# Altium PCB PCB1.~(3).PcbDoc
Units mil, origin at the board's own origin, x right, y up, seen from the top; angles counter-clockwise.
Board outline 6000 x 4000 mil, 2 copper layers (Top Layer, Bottom Layer); 43 components, 31 nets, 112 pads, 0 vias.
Unrouted connection lines stored in the file: 99.
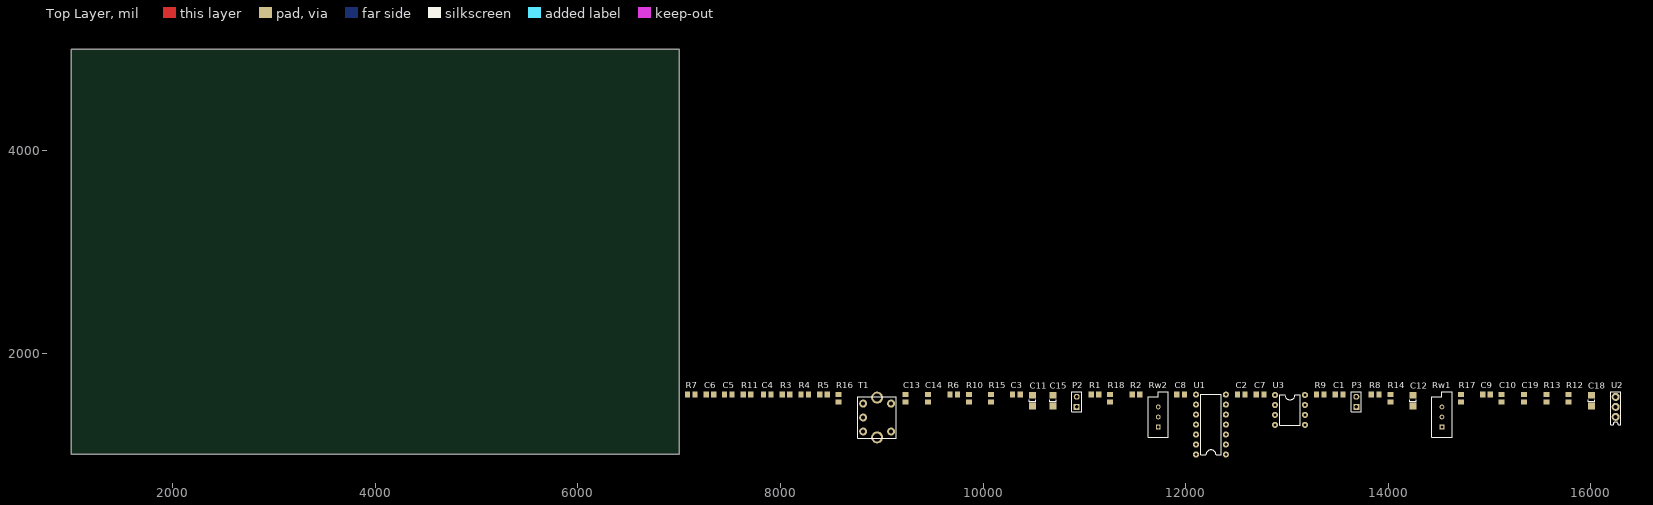
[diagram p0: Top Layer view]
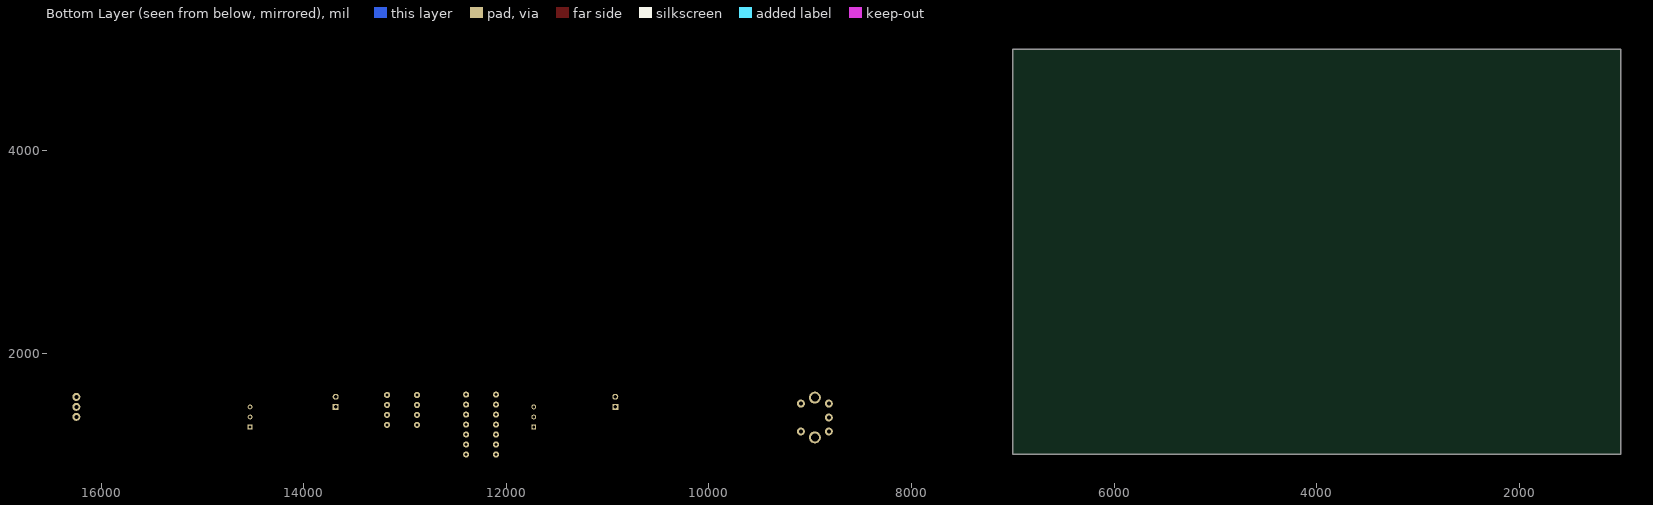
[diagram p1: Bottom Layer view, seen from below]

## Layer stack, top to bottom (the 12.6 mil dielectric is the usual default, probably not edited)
Top Layer: signal copper 1.4
Dielectric: dielectric 12.6, FR-4, Dk 4.8
Bottom Layer: signal copper 1.4

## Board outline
1000,1000 7000,1000 7000,5000 1000,5000

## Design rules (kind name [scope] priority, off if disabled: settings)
Clearance [All] p1: gap=10
PolygonConnect [All] p1: connectstyle=Relief reliefconductorwidth=10 reliefentries=4 polygonreliefangle="90 Angle"
RoomDefinition Sheet1 [InComponentClass('Sheet1')] p1: confinementstyle=ConfineIn formatcopy=TRUE lockcomponents=FALSE outline 7045,960 16315,960 16315,2560 7045,2560
RoutingVias [All] p1: holewidth=28 width=50 viastyle="Through Hole" minholewidth=28 minwidth=50 maxholewidth=28 maxwidth=50
SilkscreenOverComponentPads [All] p1: minsilkscreentomaskgap=10
SolderMaskExpansion [All] p1: expansion=4
TestPointUsage [All] p1: valid=0 allowmultiple=FALSE
Testpoint [All] p1: side=15 testpointundercomponent=TRUE minsize=40 maxsize=100 preferedsize=60 minholesize=0 maxholesize=40 preferedholesize=32 testpointgrid=1 style=1023 order=0-112345678
Width [All] p1: maxlimit=100 minlimit=10 preferedwidth=10 minimp=50.000000 maximp=50.000000 favimp=50.000000
23 further rules are at their usual default settings.

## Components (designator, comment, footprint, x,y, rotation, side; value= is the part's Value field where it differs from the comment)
C1 "Cap" 2012[0805] 13515,1590 r0 top
C2 "Cap" 2012[0805] 12550,1590 r0 top
C3 "Cap" 2012[0805] 10330,1590 r0 top
C4 "Cap" 2012[0805] 7870,1590 r0 top
C5 "Cap" 2012[0805] 7485,1590 r0 top
C6 "Cap" 2012[0805] 7305,1590 r0 top
C7 "Cap" 2012[0805] 12735,1590 r0 top
C8 "Cap" 2012[0805] 11950,1590 r0 top
C9 "Cap" 2012[0805] 14970,1590 r0 top
C10 "Cap" 2012[0805] 15120,1555 r90 top
C11 "Cap Pol1" C1206 10490,1530 r90 top
C12 "Cap Pol1" C1206 14245,1530 r90 top
C13 "Cap" 2012[0805] 9235,1555 r90 top
C14 "Cap" 2012[0805] 9455,1555 r90 top
C15 "Cap Pol1" C1206 10690,1530 r90 top
C18 "Cap Pol1" C1206 16005,1530 r90 top
C19 "Cap" 2012[0805] 15340,1555 r90 top
P2 "Header 2" HDR1X2 10925,1470 r90 top
P3 "Header 2" HDR1X2 13685,1470 r90 top
R1 "Res1" 2012[0805] 11105,1590 r0 top
R2 "Res1" 2012[0805] 11510,1590 r0 top
R3 "Res1" 2012[0805] 8055,1590 r0 top
R4 "Res1" 2012[0805] 8240,1590 r0 top
R5 "Res1" 2012[0805] 8425,1590 r0 top
R6 "Res1" 2012[0805] 9710,1590 r0 top
R7 "Res1" 2012[0805] 7120,1590 r0 top
R8 "Res1" 2012[0805] 13870,1590 r0 top
R9 "Res1" 2012[0805] 13330,1590 r0 top
R10 "Res1" 2012[0805] 9860,1555 r90 top
R11 "Res1" 2012[0805] 7670,1590 r0 top
R12 "Res1" 2012[0805] 15780,1555 r90 top
R13 "Res1" 2012[0805] 15560,1555 r90 top
R14 "Res1" 2012[0805] 14020,1555 r90 top
R15 "Res1" 2012[0805] 10080,1555 r90 top
R16 "Res1" 2012[0805] 8575,1555 r90 top
R17 "Res1" 2012[0805] 14720,1555 r90 top
R18 "Res1" 2012[0805] 11255,1555 r90 top
Rw1 "RPot" VR5 14530,1370 r90 top
Rw2 "RPot" VR5 11730,1370 r90 top
T1 "zhongzhou" zhongzhou 8955,1365 r0 top
U1 "MC1496" MC1496 12250,1295 r90 top
U2 "LM7808" LM7808 16245,1470 r90 top
U3 "LM741" LM741 13030,1440 r0 top

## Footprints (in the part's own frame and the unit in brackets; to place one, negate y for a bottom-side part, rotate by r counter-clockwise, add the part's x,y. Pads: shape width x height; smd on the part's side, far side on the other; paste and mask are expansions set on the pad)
2012[0805] [mm] "Chip Resistor; Body 2.0 x 1.3 mm (LxW typ)"
  rect 1.3x1.5 smd: 1(-0.95,0) 2(0.95,0)
C1206 [mm] "Chip Capacitor; Body 3.2 x 1.6 mm (LxW typ)"
  rect 1.6x1.8 smd: 1(-1.4,0) 2(1.4,0)
  silkscreen extent -0.3,-0.8 0.3,0.8
HDR1X2 [mm] "Connector; Header; 2 Position"
  rect 1.5x1.5 hole 0.9: 1(0,0)
  round 1.5 hole 0.9: 2(2.54,0)
  silkscreen extent -1.27,-1.27 3.81,1.27
LM741 [mil]
  round 60 hole 30: 1(-147.64,147.64) 2(-147.64,49.21) 3(-147.64,-49.21) 4(-147.64,-147.64) 5(147.64,-147.64) 6(147.64,-49.21) 7(147.64,49.21) 8(147.64,147.64)
  silkscreen extent -100,-150 100,150
LM7808 [mm]
  round 2 hole 1: 1(-2.5,0) 2(0,0) 3(2.5,0)
  silkscreen extent -4.44,-1.27 3.81,1.27
MC1496 [mil]
  round 60 hole 30: 1(-295.28,-147.64) 2(-196.85,-147.64) 3(-98.43,-147.64) 4(0,-147.64) 5(98.43,-147.64) 6(196.85,-147.64) 7(295.28,-147.64) 8(295.28,147.64) 9(196.85,147.64) 10(98.43,147.64) 11(0,147.64) 12(-98.43,147.64) 13(-196.85,147.64) 14(-295.28,147.64)
  silkscreen extent -300,-100 300,100
VR5 [mm] "Potentiometer; 3 Leads"
  rect 1.2x1.2 hole 0.7: 1(-2.54,0)
  round 1.2 hole 0.7: 2(0,0) 3(2.54,0)
  silkscreen extent -5.08,-2.54 6.35,2.54
zhongzhou [mm]
  round 2 hole 1: 1(-3.5,3.5) 2(-3.5,0) 3(-3.5,-3.5) 4(3.5,-3.5) 5(3.5,3.5)
  round 3 hole 2: 6(0,5) 7(0,-5)
  silkscreen extent -4.83,-5.21 4.83,5.21

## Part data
C1 C2 C3 C4 C5 C6 C7 C8 C9 C10 C13 C14 C19: "Capacitor"
C11 C12 C15 C18: "Polarized Capacitor (Radial)"
P2 P3: "Header, 2-Pin"
R1 R2 R3 R4 R5 R6 R7 R8 R9 R10 R11 R12 R13 R14 R15 R16 R17 R18: "Resistor"
Rw1 Rw2: "Potentiometer"

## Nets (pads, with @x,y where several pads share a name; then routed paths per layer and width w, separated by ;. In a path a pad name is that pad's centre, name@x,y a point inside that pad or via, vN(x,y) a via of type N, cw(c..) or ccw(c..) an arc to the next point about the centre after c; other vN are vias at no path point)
+12V: C18.1 R12.1
-8V: C7.2 C13.2 Rw2.3 U1.14 U3.4
GND: C4.1 C5.1 C6.1 C7.1 C8.1 C13.1 C14.1 C18.2 C19.1 P2.2 R3.1 R4.1 R7.1 R11.1 R16.1 T1.3 T1.4 T1.6 T1.7 U2.2
NetC1_1: C1.1 P3.2
NetC1_2: C1.2 C2.2 R9.1
NetC2_1: C2.1 C4.2 R10.1 T1.1
NetC3_1: C3.1 R10.2
NetC3_2: C3.2 R1.1 R3.2 U1.1
NetC5_2: C5.2 R2.1 R4.2 U1.4
NetC6_2: C6.2 C11.1 R6.1 U1.6
NetC8_2: C8.2 C12.1 R8.1 U1.12
NetC9_1: C9.1 Rw1.1 U1.8
NetC9_2: C9.2 C10.1 R12.2 R13.1 Rw1.3
NetC10_2: C10.2 R13.2
NetC11_2: C11.2 R15.1
NetC12_2: C12.2 R14.1
NetC14_2: C14.2 C15.1 R18.1
NetC15_2: C15.2 P2.1
NetC19_2: C19.2 U2.3 U3.7
NetR1_2: R1.2 Rw2.2
NetR2_2: R2.2 Rw2.1
NetR5_1: R5.1 U1.3
NetR5_2: R5.2 U1.2
NetR6_2: R6.2 R8.2 U2.1
NetR7_2: R7.2 U1.5
NetR9_2: R9.2 Rw1.2 U1.10
NetR11_2: R11.2 T1.5
NetR14_2: R14.2 R17.1 U3.2
NetR15_2: R15.2 R16.2 U3.3
NetR17_2: R17.2 R18.2 U3.6
ZHONGFANG: P3.1
pads on no net: T1.2 U1.7 U1.9 U1.11 U1.13 U3.1 U3.5 U3.8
